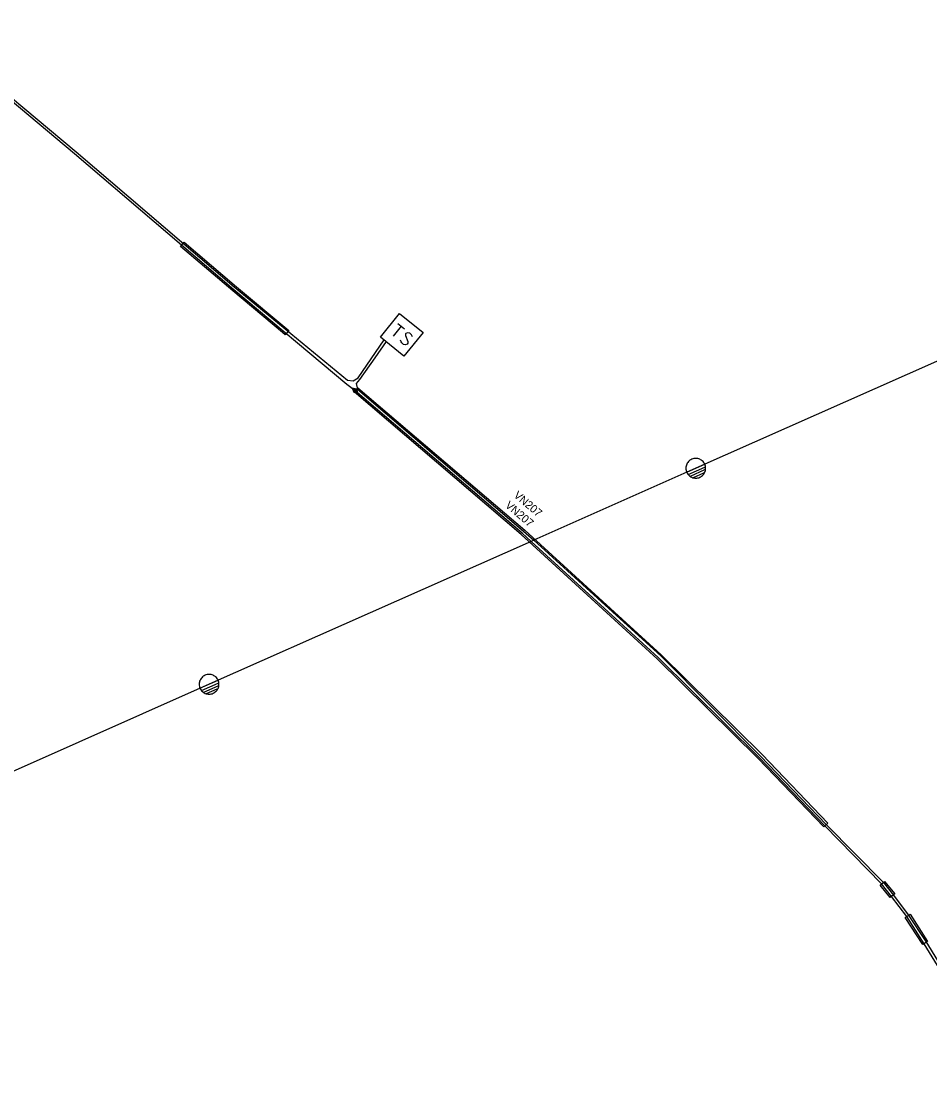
# Model space of a CAD drawing. Extents: x -643811 to -636362, y -1117362 to -1108614.
# Drawn here: x -640592.9 to -640479.9, y -1115901 to -1115769.7 of the extents above; entities that cross this region are included whole.
import ezdxf

# ---------------------------------------------------------------- set-up
doc = ezdxf.new("R2010")
doc.units = 0
for name, color, linetype in [('1', 7, 'Continuous'), ('13', 7, 'Continuous'), ('19', 7, 'Continuous'), ('20', 7, 'Continuous'), ('25', 7, 'Continuous'), ('5', 7, 'Continuous'), ('7', 7, 'Continuous')]:
    doc.layers.add(name, color=color, linetype=linetype)

# ---------------------------------------------------------------- blocks, each defined once
blk = doc.blocks.new('VN440')
at = {"layer": '13'}
for points in [[(1.22, 0), (1.21, 0.13), (1.19, 0.25), (1.16, 0.38), (1.11, 0.5), (1.05, 0.61), (0.98, 0.72), (0.9, 0.82), (0.81, 0.91), (0.71, 0.99), (0.6, 1.06), (0.49, 1.12), (0.37, 1.16), (0.25, 1.2), (0.12, 1.22), (-0.01, 1.22), (-0.14, 1.22), (-0.26, 1.2), (-0.39, 1.16), (-0.51, 1.12), (-0.62, 1.06), (-0.73, 0.99), (-0.83, 0.91), (-0.92, 0.82), (-1, 0.72), (-1.07, 0.61), (-1.13, 0.5), (-1.18, 0.38), (-1.21, 0.25), (-1.23, 0.13), (-1.24, 0), (-1.23, -0.13), (-1.21, -0.26), (-1.18, -0.38), (-1.13, -0.5), (-1.07, -0.62), (-1, -0.73), (-0.92, -0.83), (-0.83, -0.92), (-0.73, -1), (-0.62, -1.07), (-0.51, -1.13), (-0.39, -1.17), (-0.26, -1.2), (-0.14, -1.23), (-0.01, -1.23), (0.12, -1.23), (0.25, -1.2), (0.37, -1.17), (0.49, -1.13), (0.6, -1.07), (0.71, -1), (0.81, -0.92), (0.9, -0.83), (0.98, -0.73), (1.05, -0.62), (1.11, -0.5), (1.16, -0.38), (1.19, -0.26), (1.21, -0.13), (1.22, 0)], [(-1.24, 0), (1.22, 0)], [(-1.18, -0.34), (1.1, -0.34)], [(-1.01, -0.63), (0.97, -0.63)], [(-0.74, -0.92), (0.68, -0.92)]]:
    blk.add_lwpolyline(points, dxfattribs=at)
blk = doc.blocks.new('VN870')
at = {"layer": '19'}
for points in [[(0, -0.25), (0.5, 0), (0, 0.25), (-0.5, 0), (0, -0.25)], [(0.37, 0), (0, 0.19), (-0.36, 0), (0, -0.19), (0.37, 0)], [(0.24, 0), (0, 0.12), (-0.25, 0), (0, -0.12), (0.24, 0)], [(0.12, 0), (0, 0.06), (-0.13, 0), (0, -0.06), (0.12, 0)]]:
    blk.add_lwpolyline(points, dxfattribs=at)
blk = doc.blocks.new('VN640')
at = {"layer": '25'}
for points in [[(-1.89, 1.89), (1.89, 1.89)], [(-1.89, -1.89), (-1.89, 1.89)], [(1.89, 1.89), (1.89, -1.89)], [(-1.26, 0.79), (-0.22, 0.79)], [(-0.73, 0.79), (-0.73, -0.79)], [(1.2, 0.66), (0.94, 0.79), (0.66, 0.79), (0.41, 0.66), (0.28, 0.47), (0.28, 0.41), (0.41, 0.22), (1.13, -0.16), (1.26, -0.32), (1.26, -0.47), (1.13, -0.66), (0.91, -0.79), (0.63, -0.79), (0.5, -0.73), (0.28, -0.6)], [(1.89, -1.89), (-1.89, -1.89)]]:
    blk.add_lwpolyline(points, dxfattribs=at)

msp = doc.modelspace()

# ---------------------------------------------------------------- linework, layer by layer
at = {"layer": '1'}
msp.add_lwpolyline([(-640174.13, -1115803.89), (-640251.81, -1115797.69), (-640320.19, -1115797.01), (-640382.28, -1115796.07), (-640441.87, -1115795.49), (-640509.03, -1115825.24), (-640529.18, -1115834.18), (-640529.51, -1115834.33), (-640569.54, -1115852.09), (-640642.67, -1115884.59), (-640695.7, -1115908.15), (-640695.88, -1115908.23), (-640712.05, -1115915.41), (-640778.4, -1115945.12), (-640781.72, -1115942.1), (-640781.89, -1115941.95), (-640782.05, -1115941.8), (-640782.21, -1115941.65), (-640782.37, -1115941.51), (-640806.72, -1115919.38), (-640845, -1115909.84)], dxfattribs=at)
at = {"layer": '20'}
for points in [[(-640572.63, -1115797.14), (-640566.13, -1115802.68), (-640559.62, -1115808.13), (-640560.07, -1115808.66), (-640560.41, -1115808.38), (-640566.58, -1115803.21), (-640573.08, -1115797.67), (-640572.87, -1115797.42)], [(-640493.11, -1115869.83), (-640501.29, -1115861.32), (-640513.83, -1115848.93), (-640530.76, -1115833.46), (-640551.51, -1115815.77), (-640551.06, -1115815.24), (-640530.3, -1115832.94), (-640513.34, -1115848.42), (-640500.79, -1115860.83), (-640492.61, -1115869.34)], [(-640484.3, -1115878.15), (-640484.85, -1115878.59), (-640486.1, -1115877.04), (-640485.55, -1115876.6)], [(-640480.23, -1115884.07), (-640480.82, -1115884.45), (-640482.98, -1115881.06), (-640482.39, -1115880.68)]]:
    msp.add_lwpolyline(points, close=True, dxfattribs=at)
at = {"layer": '5'}
for points in [[(-640551.38, -1115815.62), (-640552.4, -1115814.82), (-640566.45, -1115803.06), (-640586.28, -1115786.16), (-640605.66, -1115769.93)], [(-640605.49, -1115769.68), (-640586.08, -1115785.91), (-640566.41, -1115802.72), (-640552.35, -1115814.31), (-640551.62, -1115814.4), (-640551, -1115814.02), (-640547.77, -1115809.29)], [(-640547.54, -1115809.48), (-640548.93, -1115811.53), (-640550.83, -1115814.2), (-640551.25, -1115814.71), (-640551.1, -1115815.41), (-640530.43, -1115833.05), (-640529.18, -1115834.18), (-640513.35, -1115848.58), (-640501, -1115861.01), (-640492.82, -1115869.51), (-640485.7, -1115876.73), (-640484.45, -1115878.29), (-640482.62, -1115880.76), (-640480.41, -1115884.06), (-640471.15, -1115899.17)], [(-640430.62, -1115980.3), (-640430.34, -1115980.04), (-640432.1, -1115975.76), (-640433.89, -1115973.23), (-640436.64, -1115966.9), (-640438.03, -1115964.35), (-640441.33, -1115958.39), (-640447.9, -1115943.11), (-640452.56, -1115932.41), (-640460.01, -1115918.43), (-640471.38, -1115899.36), (-640480.65, -1115884.34), (-640482.81, -1115880.95), (-640484.69, -1115878.46), (-640485.94, -1115876.91), (-640492.97, -1115869.69), (-640501.15, -1115861.18), (-640513.69, -1115848.78), (-640529.51, -1115834.33), (-640530.63, -1115833.31), (-640551.38, -1115815.62)]]:
    msp.add_lwpolyline(points, dxfattribs=at)

# ---------------------------------------------------------------- block references
at = {"layer": '13', "rotation": 24}
for p in [(-640509.03, -1115825.24), (-640569.54, -1115852.09)]:
    msp.add_blockref('VN440', p, dxfattribs=at)
at = {"layer": '19', "rotation": -40.00000000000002}
msp.add_blockref('VN870', (-640551.38, -1115815.62), dxfattribs=at)
at = {"layer": '25', "rotation": -39.00000000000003}
msp.add_blockref('VN640', (-640545.59, -1115808.67), dxfattribs=at)

# ---------------------------------------------------------------- texts
at = {"layer": '7'}
for rotation, p in [(319.5222, (-640531.75, -1115828.74)), (319.5514, (-640532.81, -1115829.99))]:
    msp.add_text('VN207', height=0.994, rotation=rotation, dxfattribs=at).set_placement(p)

doc.saveas('drawing.dxf')
